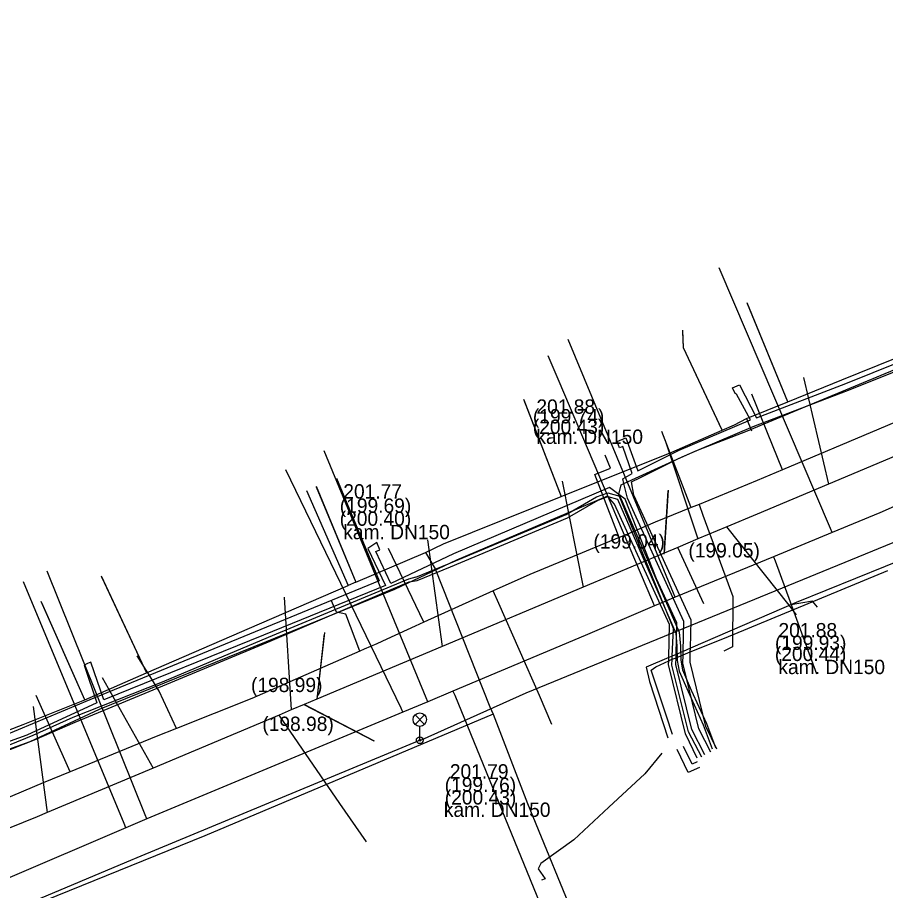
# Model space of a CAD drawing. Extents: x -596228 to -595156, y -1161235 to -1159373.
# Drawn here: x -595969.34 to -595920.94, y -1160772.62 to -1160723.93 of the extents above; entities that cross this region are included whole.
import ezdxf

# ---------------------------------------------------------------- set-up
doc = ezdxf.new("R2010")
doc.units = 0
for name, color, linetype in [('Vrstva 1', 7, 'Continuous'), ('Vrstva 12', 7, 'Continuous'), ('Vrstva 14', 7, 'Continuous'), ('Vrstva 19', 7, 'Continuous'), ('Vrstva 33', 7, 'Continuous'), ('Vrstva 42', 7, 'Continuous'), ('Vrstva 44', 7, 'Continuous'), ('Vrstva 55', 7, 'Continuous'), ('Vrstva 58', 7, 'Continuous'), ('Vrstva 9', 7, 'Continuous')]:
    doc.layers.add(name, color=color, linetype=linetype)

msp = doc.modelspace()

# ---------------------------------------------------------------- linework, layer by layer
at = {"layer": 'Vrstva 1'}
for p, q in [((-595933.075, -1160750.334), (-595933.297, -1160753.87)), ((-595933.06, -1160750.3), (-595933.288, -1160753.812)), ((-595931.08, -1160756.63), (-595932.513, -1160753.484)), ((-595931.08, -1160756.63), (-595932.512, -1160753.484)), ((-595952.22, -1160758.23), (-595952.645, -1160761.95)), ((-595949.45, -1160764.286), (-595953.357, -1160762.268)), ((-595949.44, -1160764.3), (-595953.355, -1160762.249))]:
    msp.add_line(p, q, dxfattribs=at)
for points in [[(-595924.73, -1160756.81), (-595925.01, -1160756.48), (-595926.316, -1160756.714)], [(-595952.284, -1160758.39), (-595952.255, -1160758.462), (-595952.641, -1160761.954)]]:
    msp.add_lwpolyline(points, dxfattribs=at)
at = {"layer": 'Vrstva 12'}
for p, q in [((-595926.38, -1160745.37), (-595928.63, -1160739.91)), ((-595941.11, -1160745.25), (-595939.03, -1160750.64)), ((-595928.7, -1160746.3), (-595926.38, -1160745.37)), ((-595928.7, -1160746.3), (-595928.42, -1160746.98)), ((-595953.23, -1160750.32), (-595950.91, -1160755.62)), ((-595952.68, -1160750.1), (-595950.48, -1160755.43)), ((-595950.48, -1160755.43), (-595946.59, -1160753.77)), ((-595964.68, -1160755.08), (-595962.15, -1160760.48)), ((-595950.48, -1160755.43), (-595950.91, -1160755.62)), ((-595965.59, -1160761.98), (-595968.02, -1160756.51)), ((-595965.59, -1160761.98), (-595962.15, -1160760.48))]:
    msp.add_line(p, q, dxfattribs=at)
for points in [[(-595926.38, -1160745.37), (-595923.37, -1160744.15), (-595918.35, -1160742.11), (-595916.16, -1160741.11), (-595915.46, -1160740.82)], [(-595930.04, -1160746.94), (-595932.21, -1160742.36), (-595932.24, -1160741.46)], [(-595930.04, -1160746.94), (-595929.36, -1160746.65), (-595928.7, -1160746.3)], [(-595939.03, -1160750.64), (-595932.86, -1160748.17), (-595930.04, -1160746.94)], [(-595951.56, -1160749.63), (-595949.17, -1160755.35), (-595965.3, -1160761.99), (-595972.52, -1160765)], [(-595946.59, -1160753.77), (-595945.59, -1160753.28), (-595939.03, -1160750.64)], [(-595946.59, -1160753.77), (-595946.05, -1160754.68), (-595943.01, -1160762.37), (-595942.82, -1160762.79)], [(-595962.15, -1160760.48), (-595955.85, -1160757.74), (-595950.91, -1160755.62)], [(-595978.8, -1160767.38), (-595971.58, -1160764.35), (-595969.02, -1160763.37), (-595965.59, -1160761.98)], [(-595942.82, -1160762.79), (-595958.9, -1160769.57), (-595967.83, -1160773.2), (-595967.34, -1160774.36)], [(-595942.82, -1160762.79), (-595940.91, -1160767.77), (-595938.03, -1160774.79)]]:
    msp.add_lwpolyline(points, dxfattribs=at)
at = {"layer": 'Vrstva 14'}
for points in [[(-595923.91, -1160752.66), (-595924.01, -1160752.43), (-595930.211, -1160737.903)], [(-595895.93, -1160740.59), (-595899.6, -1160742.31), (-595912.84, -1160747.84), (-595914.74, -1160748.68), (-595921.25, -1160751.56), (-595923.91, -1160752.66), (-595927.19, -1160754.01), (-595932.66, -1160756.26), (-595933.82, -1160756.75), (-595937.68, -1160758.4), (-595942.37, -1160760.37), (-595945.06, -1160761.51), (-595946.46, -1160762.1), (-595947.85, -1160762.68), (-595962.12, -1160768.63), (-595963.29, -1160769.12), (-595970.02, -1160772), (-595976.93, -1160774.96), (-595977.43, -1160775.17), (-595987.69, -1160779.56), (-595997.69, -1160783.61)], [(-595932.66, -1160756.26), (-595932.76, -1160756.03), (-595938.629, -1160741.9)], [(-595933.82, -1160756.75), (-595933.92, -1160756.52), (-595939.19, -1160744.102), (-595939.742, -1160742.801)], [(-595946.46, -1160762.1), (-595946.56, -1160761.87), (-595952.237, -1160748.094)], [(-595947.85, -1160762.68), (-595947.95, -1160762.45), (-595954.371, -1160749.17)], [(-595927.19, -1160754.01), (-595927.09, -1160754.24), (-595924.791, -1160760.533)], [(-595962.12, -1160768.63), (-595962.22, -1160768.4), (-595967.681, -1160754.805)], [(-595963.29, -1160769.12), (-595963.39, -1160768.89), (-595969.002, -1160755.406)], [(-595945.06, -1160761.51), (-595944.95, -1160761.73), (-595939.874, -1160774.143)]]:
    msp.add_lwpolyline(points, dxfattribs=at)
at = {"layer": 'Vrstva 19'}
for p, q in [((-595926.69, -1160749.17), (-595928.39, -1160744.94)), ((-595946.69, -1160757.66), (-595948.65, -1160753.54)), ((-595951.72, -1160756.73), (-595951.831, -1160756.463)), ((-595966.4, -1160766), (-595968.29, -1160761.74))]:
    msp.add_line(p, q, dxfattribs=at)
for points in [[(-595916.09, -1160744.68), (-595921.31, -1160746.9), (-595926.69, -1160749.17), (-595928.09, -1160749.76), (-595931.34, -1160751.09), (-595931.77, -1160751.26), (-595933.79, -1160752.08), (-595935.45, -1160752.8), (-595935.8, -1160752.94), (-595940.78, -1160754.99), (-595942.82, -1160755.91), (-595946.69, -1160757.66), (-595947.16, -1160757.87), (-595948.74, -1160758.61), (-595949.31, -1160758.87), (-595950.01, -1160759.17), (-595950.26, -1160759.27), (-595956.27, -1160761.91), (-595960.48, -1160763.58), (-595961.6, -1160764.03), (-595966.4, -1160766), (-595967.9, -1160766.61), (-595974.54, -1160769.42)], [(-595931.77, -1160751.26), (-595931.787, -1160751.217), (-595933.42, -1160747.03)], [(-595935.8, -1160752.94), (-595937.14, -1160749.43), (-595936.27, -1160749.06), (-595936.58, -1160748.35)], [(-595931.34, -1160751.09), (-595931.13, -1160751.68), (-595929.45, -1160756.22), (-595929.48, -1160759.04), (-595929.95, -1160759.27)], [(-595939.54, -1160763.36), (-595940.24, -1160761.74), (-595942.51, -1160756.62), (-595942.82, -1160755.91)], [(-595950.26, -1160759.27), (-595951.04, -1160757.21), (-595951.56, -1160757.09), (-595951.72, -1160756.73)], [(-595960.48, -1160763.58), (-595961.44, -1160761.5), (-595961.67, -1160761.13), (-595962.66, -1160759.53)]]:
    msp.add_lwpolyline(points, dxfattribs=at)
at = {"layer": 'Vrstva 33'}
for p, q in [((-595947.175, -1160762.825), (-595946.645, -1160763.355)), ((-595947.175, -1160763.355), (-595946.645, -1160762.825)), ((-595946.91, -1160764.24), (-595946.91, -1160763.465))]:
    msp.add_line(p, q, dxfattribs=at)
for centre, radius in [((-595946.91, -1160763.09), 0.375), ((-595946.91, -1160764.24), 0.19), ((-595946.91, -1160764.24), 0.05)]:
    msp.add_circle(centre, radius, dxfattribs=at)
at = {"layer": 'Vrstva 42'}
for points in [[(-595934.6, -1160749.584), (-595932.554, -1160748.571), (-595932.27, -1160748.43), (-595931.848, -1160748.25), (-595931.34, -1160748.035), (-595928.323, -1160746.752), (-595925.354, -1160745.618), (-595923.01, -1160744.723), (-595918.328, -1160742.842), (-595916.894, -1160742.204), (-595916.001, -1160741.822), (-595910.627, -1160739.525), (-595898.834, -1160734.62), (-595898.036, -1160732.667), (-595898, -1160732.327), (-595897.967, -1160732.02), (-595902.348, -1160723.934), (-595907.114, -1160726.226)], [(-595874.569, -1160738.85), (-595882.702, -1160741.846), (-595889.513, -1160744.047), (-595891.393, -1160744.454), (-595894.802, -1160744.39), (-595902.471, -1160746.816), (-595915.993, -1160752.54), (-595925.914, -1160756.568), (-595931.82, -1160759.113), (-595932.225, -1160759.288), (-595932.613, -1160759.455), (-595932.828, -1160759.547), (-595933.027, -1160759.633), (-595934.282, -1160760.174), (-595934.102, -1160760.967), (-595933.081, -1160764.099)], [(-595930.688, -1160764.9), (-595931.341, -1160763.609), (-595932.243, -1160759.936), (-595932.231, -1160759.481), (-595932.225, -1160759.288), (-595932.18, -1160757.617), (-595935.33, -1160750.742), (-595935.526, -1160749.918), (-595935.587, -1160749.664), (-595935.067, -1160749.358), (-595935.588, -1160747.867), (-595935.764, -1160747.929), (-595935.911, -1160747.59), (-595935.421, -1160747.375), (-595934.742, -1160749.215), (-595932.437, -1160748.066), (-595928.473, -1160746.381), (-595929.251, -1160744.934), (-595929.333, -1160744.896), (-595929.473, -1160744.587), (-595929.08, -1160744.413), (-595928.136, -1160746.258), (-595923.156, -1160744.351), (-595918.484, -1160742.474)], [(-595931.188, -1160765.181), (-595931.933, -1160763.774), (-595932.849, -1160760.047), (-595932.835, -1160759.724), (-595932.828, -1160759.547), (-595932.764, -1160758.015), (-595935.812, -1160750.56), (-595935.807, -1160750.536), (-595935.687, -1160749.991), (-595935.526, -1160749.918), (-595932.554, -1160748.571), (-595931.848, -1160748.25), (-595931.56, -1160748.12), (-595931.34, -1160748.035), (-595928.724, -1160747.019), (-595925.354, -1160745.618), (-595918.221, -1160742.653)], [(-595930.34, -1160764.744), (-595930.963, -1160763.472), (-595931.841, -1160759.893), (-595931.825, -1160759.318), (-595931.82, -1160759.113), (-595931.777, -1160757.535), (-595934.967, -1160750.576), (-595935.108, -1160749.829), (-595934.6, -1160749.584)], [(-595931.022, -1160765.05), (-595931.746, -1160763.632), (-595932.623, -1160760.021), (-595932.616, -1160759.636), (-595932.613, -1160759.455), (-595932.582, -1160757.699), (-595933.713, -1160755.238), (-595935.46, -1160750.795), (-595935.807, -1160750.536), (-595936.337, -1160750.141), (-595945.025, -1160753.841), (-595948.514, -1160755.499), (-595949.358, -1160753.72), (-595949.135, -1160753.618), (-595949.3, -1160753.205), (-595949.807, -1160753.554), (-595948.821, -1160755.608), (-595955.629, -1160758.375), (-595964.531, -1160761.996), (-595965.255, -1160759.888), (-595965.431, -1160759.96), (-595965.622, -1160760.054), (-595964.909, -1160762.151), (-595968.81, -1160763.953), (-595975.491, -1160766.36)], [(-595936.437, -1160750.624), (-595944.861, -1160754.206), (-595948.324, -1160755.834), (-595955.478, -1160758.746), (-595964.783, -1160762.531), (-595968.658, -1160764.323), (-595975.348, -1160766.734), (-595979.104, -1160768.254), (-595980.872, -1160769.232), (-595986.529, -1160771.469), (-596002.845, -1160778.125), (-596002.718, -1160778.924), (-595999.968, -1160785.818), (-596000.123, -1160790.427), (-595995.215, -1160804.501), (-595993.599, -1160808.162)], [(-595931.436, -1160765.236), (-595932.097, -1160763.884), (-595933.036, -1160760.008), (-595933.031, -1160759.807), (-595933.027, -1160759.633), (-595932.984, -1160757.781), (-595936.058, -1160751.075), (-595936.437, -1160750.624)], [(-595932.809, -1160763.924), (-595933.146, -1160762.893), (-595934.009, -1160760.333), (-595933.743, -1160760.143), (-595933.031, -1160759.807), (-595932.972, -1160759.779), (-595932.835, -1160759.724), (-595932.616, -1160759.636), (-595932.231, -1160759.481), (-595931.825, -1160759.318), (-595929.91, -1160758.548), (-595920.807, -1160754.77)], [(-595931.446, -1160765.444), (-595931.713, -1160765.57), (-595932.21, -1160764.584)], [(-595933.406, -1160764.964), (-595934.359, -1160766.112), (-595936.366, -1160767.969), (-595938.314, -1160769.79), (-595940.16, -1160771.106), (-595940.302, -1160771.419), (-595939.926, -1160771.96), (-595940.131, -1160772.046)], [(-595931.305, -1160765.757), (-595931.939, -1160766.03), (-595932.561, -1160764.756)]]:
    msp.add_lwpolyline(points, dxfattribs=at)
at = {"layer": 'Vrstva 44'}
for points in [[(-595947.138, -1160755.147), (-595945.268, -1160754.388), (-595938.755, -1160751.65), (-595937.052, -1160750.669), (-595936.423, -1160750.445), (-595935.747, -1160750.637), (-595932.442, -1160758.215), (-595932.37, -1160758.985), (-595932.36, -1160759.77), (-595932.254, -1160760.32), (-595931.768, -1160761.45), (-595930.928, -1160763.312), (-595930.417, -1160764.654)], [(-595947.062, -1160755.333), (-595945.192, -1160754.572), (-595938.666, -1160751.83), (-595936.968, -1160750.851), (-595936.416, -1160750.655), (-595935.893, -1160750.803), (-595932.638, -1160758.265), (-595932.57, -1160758.995), (-595932.56, -1160759.79), (-595932.446, -1160760.38), (-595931.951, -1160761.53), (-595931.112, -1160763.388), (-595930.603, -1160764.726)], [(-595947.138, -1160755.147), (-595947.53, -1160755.263), (-595955.361, -1160758.509), (-595961.279, -1160761.006), (-595966.257, -1160762.968), (-595968.492, -1160763.968), (-595978.248, -1160767.963), (-595982.038, -1160769.681), (-595983.515, -1160770.213), (-595986.68, -1160771.502), (-595988.239, -1160772.436), (-596001.296, -1160777.768), (-596002.534, -1160778.092), (-596002.636, -1160778.737), (-596000.076, -1160786.064), (-596000.212, -1160788.42), (-595994.428, -1160804.351), (-595993.163, -1160808.12)], [(-595992.914, -1160808.002), (-595994.102, -1160804.235), (-595996.628, -1160797.175), (-595999.888, -1160788.242), (-595999.901, -1160785.985), (-596002.42, -1160778.617), (-596002.297, -1160778.256), (-596001.26, -1160777.87), (-595988.213, -1160772.576), (-595986.599, -1160771.708), (-595983.467, -1160770.39), (-595982.005, -1160769.834), (-595978.161, -1160768.068), (-595968.389, -1160764.21), (-595966.12, -1160763.24), (-595961.236, -1160761.203), (-595955.248, -1160758.714), (-595947.498, -1160755.415), (-595947.062, -1160755.333)]]:
    msp.add_lwpolyline(points, dxfattribs=at)
at = {"layer": 'Vrstva 55'}
msp.add_lwpolyline([(-595970.72, -1160774.17), (-595963.24, -1160771.03), (-595962.45, -1160770.68), (-595946.91, -1160764.24), (-595946.81, -1160764.21), (-595940.98, -1160761.6), (-595935.62, -1160759.4), (-595918.979, -1160752.583), (-595918.84, -1160752.59), (-595918.84, -1160752.526), (-595917.36, -1160751.92), (-595897.49, -1160743.44), (-595896.144, -1160743), (-595896.08, -1160742.95), (-595895.99, -1160742.95), (-595895.02, -1160742.92), (-595890.5, -1160745.95), (-595889.82, -1160746.14), (-595889.665, -1160746.088)], dxfattribs=at)
at = {"layer": 'Vrstva 58'}
for p, q in [((-595926.38, -1160745.37), (-595928.65, -1160739.85)), ((-595941.13, -1160745.22), (-595939.03, -1160750.64)), ((-595928.7, -1160746.3), (-595926.38, -1160745.37)), ((-595928.7, -1160746.3), (-595928.42, -1160746.98)), ((-595932.86, -1160748.17), (-595930.04, -1160746.94)), ((-595939.03, -1160750.64), (-595932.86, -1160748.17)), ((-595953.23, -1160750.31), (-595950.91, -1160755.62)), ((-595952.68, -1160750.08), (-595950.48, -1160755.43)), ((-595950.48, -1160755.43), (-595946.59, -1160753.77)), ((-595964.66, -1160755.12), (-595962.15, -1160760.48)), ((-595950.48, -1160755.43), (-595950.91, -1160755.62)), ((-595965.59, -1160761.98), (-595967.99, -1160756.57)), ((-595965.59, -1160761.98), (-595962.15, -1160760.48))]:
    msp.add_line(p, q, dxfattribs=at)
for points in [[(-595926.38, -1160745.37), (-595923.37, -1160744.15), (-595918.35, -1160742.11), (-595916.16, -1160741.11), (-595915.46, -1160740.82)], [(-595930.06, -1160746.91), (-595932.21, -1160742.36), (-595932.24, -1160741.37)], [(-595930.04, -1160746.94), (-595929.36, -1160746.65), (-595928.7, -1160746.3)], [(-595946.59, -1160753.77), (-595945.59, -1160753.28), (-595939.03, -1160750.64)], [(-595946.59, -1160753.77), (-595946.05, -1160754.68), (-595943.01, -1160762.37), (-595942.82, -1160762.79)], [(-595962.15, -1160760.48), (-595955.85, -1160757.74), (-595950.91, -1160755.62)], [(-595978.8, -1160767.38), (-595971.58, -1160764.35), (-595969.02, -1160763.37), (-595965.59, -1160761.98)], [(-595942.82, -1160762.79), (-595958.9, -1160769.57), (-595967.83, -1160773.2), (-595967.34, -1160774.36)], [(-595942.82, -1160762.79), (-595940.91, -1160767.77), (-595938.03, -1160774.79)]]:
    msp.add_lwpolyline(points, dxfattribs=at)
at = {"layer": 'Vrstva 9'}
for p, q in [((-595925.519, -1160744.013), (-595924.115, -1160749.953)), ((-595933.24, -1160747.475), (-595931.397, -1160753.015)), ((-595938.971, -1160749.799), (-595937.804, -1160755.709)), ((-595946.471, -1160753.06), (-595945.667, -1160759.016)), ((-595954.478, -1160756.262), (-595954.074, -1160762.551)), ((-595964.61, -1160760.75), (-595961.78, -1160765.792)), ((-595968.466, -1160762.353), (-595967.689, -1160768.276)), ((-595951.37, -1160767.77), (-595954.756, -1160762.838)), ((-595949.883, -1160769.903), (-595951.37, -1160767.77))]:
    msp.add_line(p, q, dxfattribs=at)
for points in [[(-595889.188, -1160735.27), (-595906.245, -1160742.44), (-595909.361, -1160743.75), (-595914.85, -1160746.058), (-595924.115, -1160749.953), (-595928.103, -1160751.629)], [(-595928.103, -1160751.629), (-595929.784, -1160752.336), (-595931.397, -1160753.015), (-595932.513, -1160753.484), (-595933.288, -1160753.812), (-595937.804, -1160755.709), (-595945.667, -1160759.016), (-595952.645, -1160761.95), (-595953.355, -1160762.249), (-595954.074, -1160762.551), (-595954.756, -1160762.838), (-595961.78, -1160765.792), (-595967.689, -1160768.276), (-595968.251, -1160768.513)], [(-595925.9, -1160757.24), (-595926.316, -1160756.714), (-595929.784, -1160752.336)], [(-595968.251, -1160768.513), (-595971.386, -1160769.775), (-595974.531, -1160771.04), (-595983.15, -1160774.508), (-595997.808, -1160780.406), (-595998.541, -1160780.7), (-595999.654, -1160781.148)]]:
    msp.add_lwpolyline(points, dxfattribs=at)

# ---------------------------------------------------------------- texts
at = {"layer": 'Vrstva 12'}
for s, p in [('201.88', (-595940.407, -1160746.035)), ('(199.74)', (-595940.602, -1160746.572)), ('(200.43)', (-595940.607, -1160747.154)), ('kam. DN150', (-595940.409, -1160747.714)), ('201.77', (-595951.173, -1160750.762)), ('(199.69)', (-595951.369, -1160751.558)), ('(200.40)', (-595951.373, -1160752.28)), ('kam. DN150', (-595951.176, -1160753.03)), ('(199.04)', (-595937.228, -1160753.555)), ('(199.05)', (-595931.931, -1160754.048)), ('201.88', (-595926.911, -1160758.504)), ('(199.93)', (-595927.106, -1160759.201)), ('(200.44)', (-595927.11, -1160759.823)), ('kam. DN150', (-595926.913, -1160760.553)), ('(198.99)', (-595956.319, -1160761.554)), ('(198.98)', (-595955.688, -1160763.724)), ('201.79', (-595945.234, -1160766.376)), ('(199.76)', (-595945.519, -1160767.122)), ('(200.43)', (-595945.514, -1160767.824)), ('kam. DN150', (-595945.566, -1160768.514))]:
    msp.add_text(s, height=0.8, dxfattribs=at).set_placement(p)

doc.saveas('drawing.dxf')
